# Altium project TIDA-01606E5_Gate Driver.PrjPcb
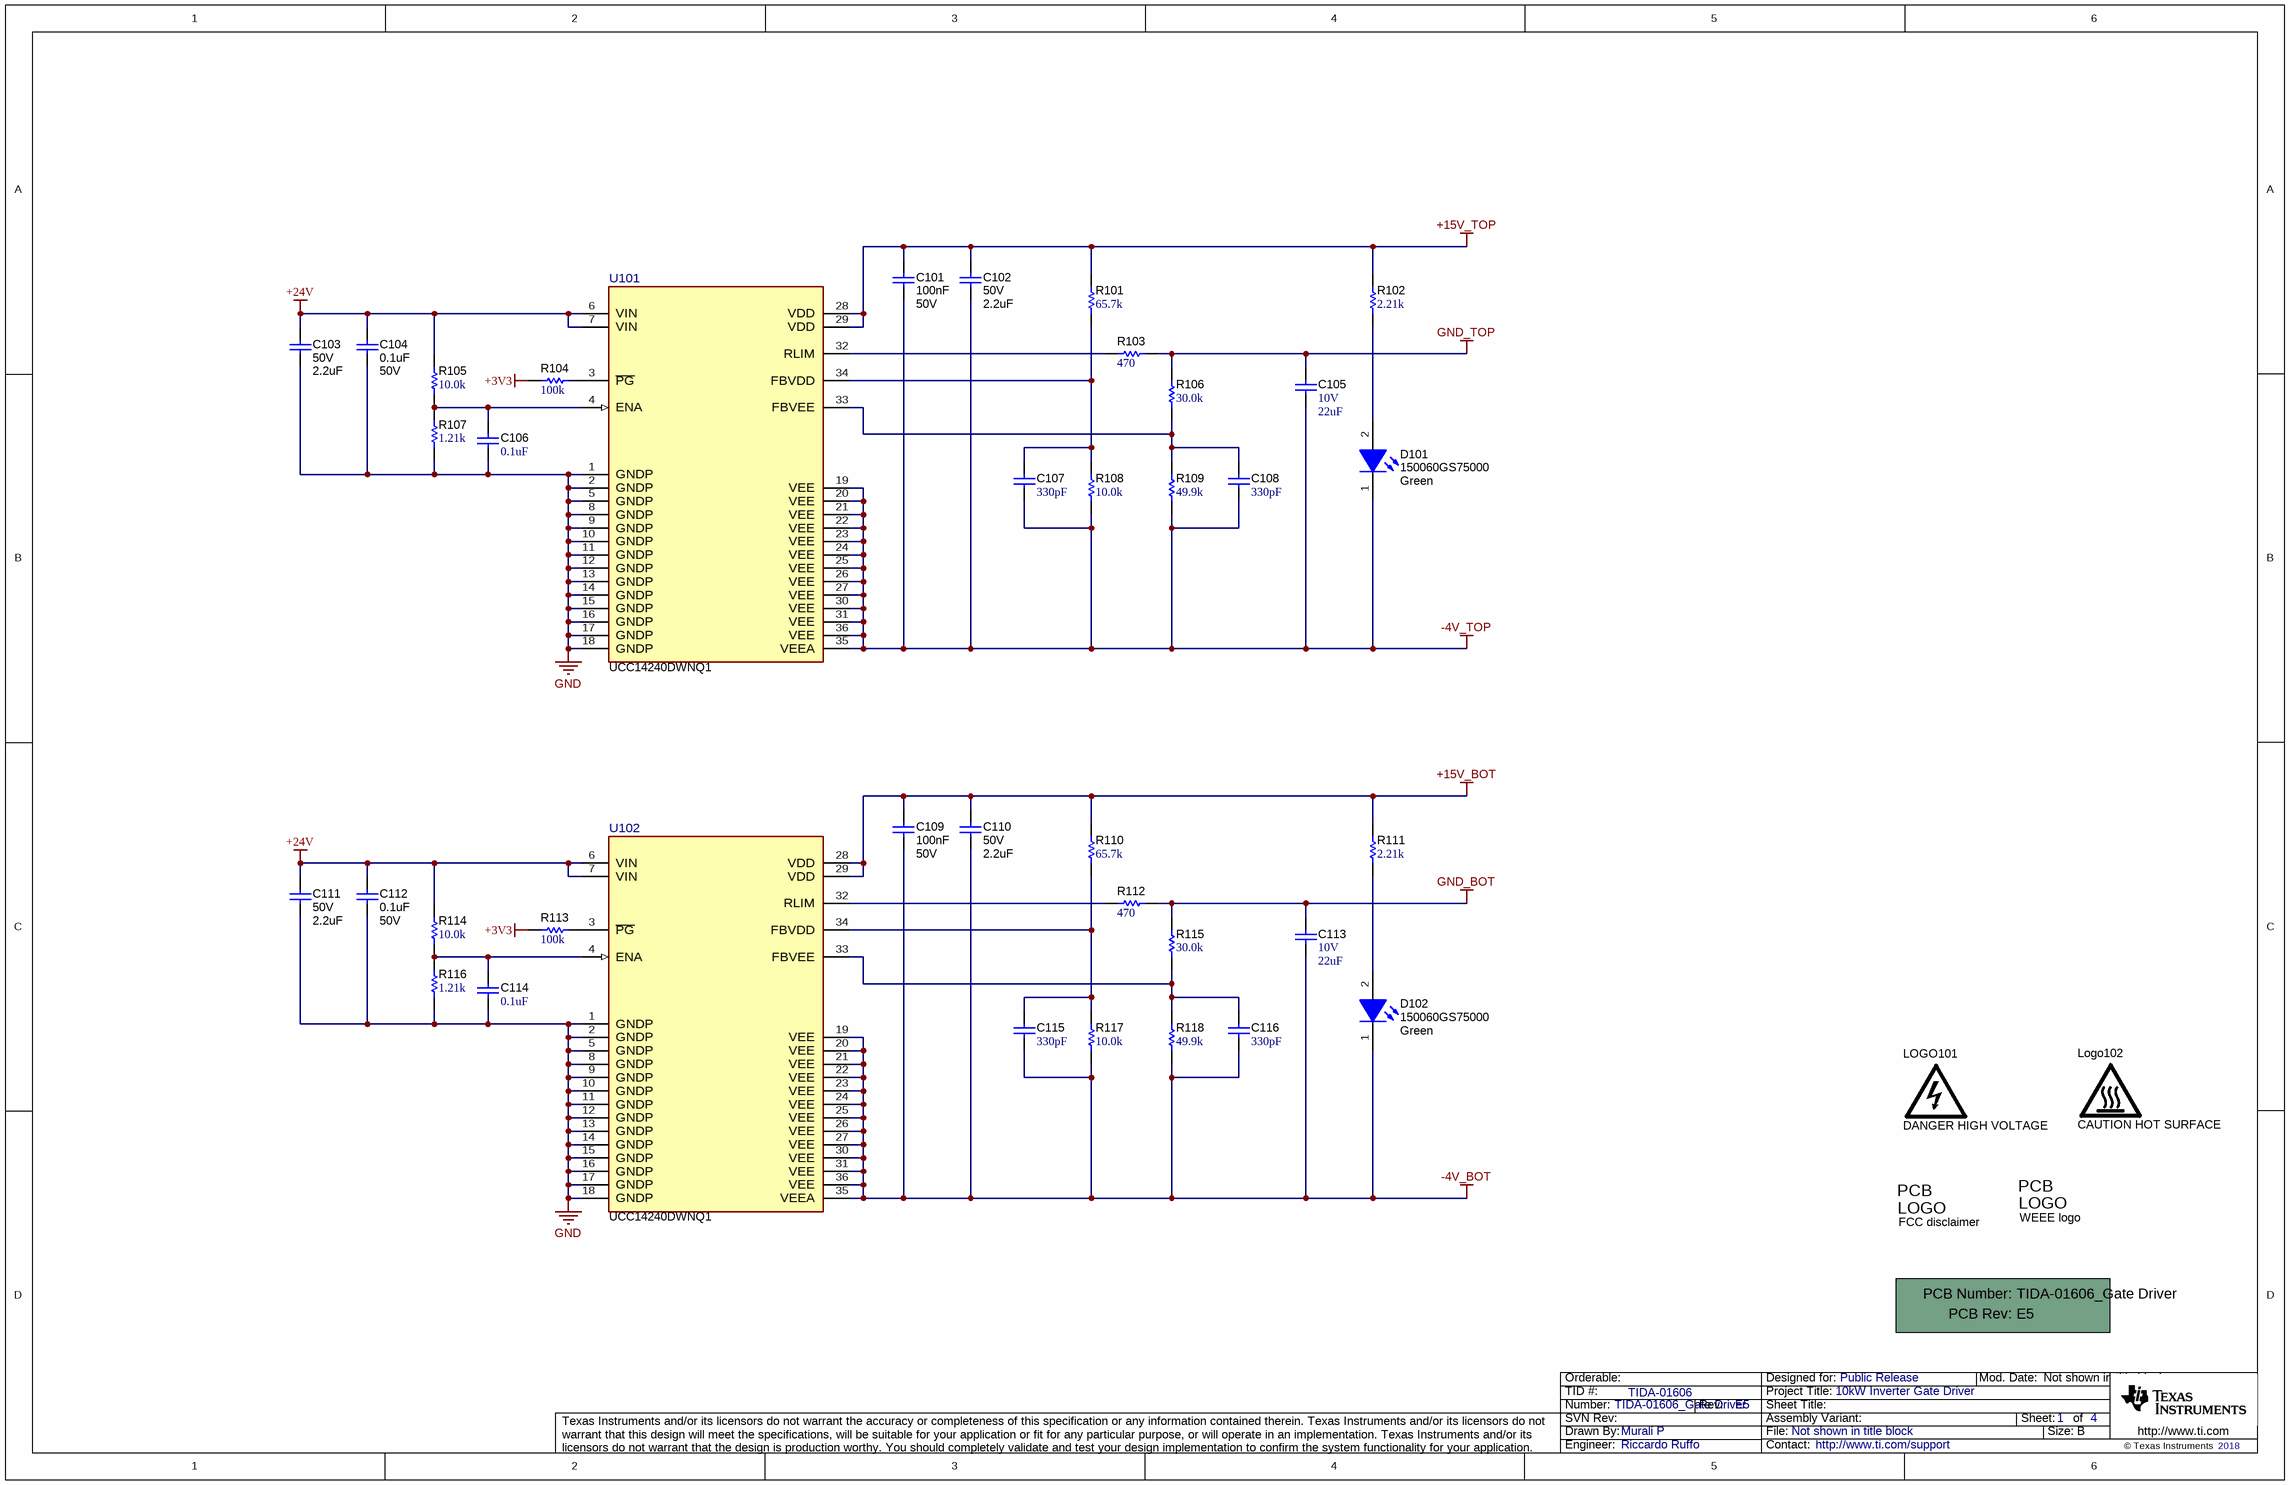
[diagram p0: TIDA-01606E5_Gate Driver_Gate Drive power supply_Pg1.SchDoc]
Drawn By: Riccardo Ruffo; TID: TIDA-01606; TechSupport: http://www.ti.com/support; SCH_Rev: E5; PRJ_Title: 10kW Inverter Gate Driver; PRJ_Number: TIDA-01606_Gate Driver; PRJ_Engineer: Riccardo Ruffo; PRJ_Customer: Public Release; PCB_Rev: E5; PCB_Layout: John Dorosa; CopyrightYear: 2018
4 sheets, 185 parts. Net scope: global (net labels, ports and power ports of the same name join across sheets).
Board file: TIDA-01606E5_Gate Driver_PCB.PcbDoc
Sheets:
  TIDA-01606E5_Gate Driver_Gate Drive power supply_Pg1.SchDoc
  TIDA-01606E5_Gate Driver_Gate Drive power supply_Pg2.SchDoc
  TIDA-01606E5_Gate Driver_Isolated Gate Driver_Pg3.SchDoc
  TIDA-01606E5_Gate Driver_Isolated Gate Driver_Pg4.SchDoc

## Sheet TIDA-01606E5_Gate Driver_Gate Drive power supply_Pg1.SchDoc
size 431 x 279 mm; Date: Not shown in title block; ApprovedBy: Not shown in title block; CheckedBy: Not shown in title block; Author: Not shown in title block; CompanyName: Not shown in title block; DrawnBy: Murali P; Engineer: Not shown in title block; Organization: Not shown in title block; Address1: Not shown in title block; Address2: Not shown in title block; Address3: Not shown in title block; Address4: Not shown in title block; DocumentNumber: 1; Revision: Use project parameter SCH_Rev; SheetNumber: 1; SheetTotal: 4; PageSetup: Record=PageOptions¦CenterHorizontal=True¦CenterVertical=True¦PrintScale=1.00¦XCorrection=1.00¦YCorrection=1.00¦PrintKind=0¦BorderSize=5000000¦LeftOffset=0¦BottomOffset=0¦Orientation=2¦PaperLength=1000¦PaperWidth=1000¦Scale=100¦PaperSource=15¦PrintQuality=600¦MediaType=1¦DitherType=10¦PaperKind=Letter¦PrintScaleMode=1

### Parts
!PCB101  Printed Circuit Board  (value not drawn)  (mechanical)
C101  Cap_F: 100nF  VDC_V: 50V  [0603]  (hidden comment: CGA3E2X7R1H104K080AA)
C102  VDC_V: 50V  ValueDisplayed: 2.2uF  [1210_280]  (hidden comment: C3225X7R1H225K250AB)
C103  VDC_V: 50V  ValueDisplayed: 2.2uF  [1210_280]  (hidden comment: C3225X7R1H225K250AB)
C104  value 0.1uF  VDC_V: 50V  [0603]  (hidden comment: CGA3E2X7R1H104K080AA)
C105  VDC_V: 10V  ValueDisplayed: 22uF  [1206_180L]  (hidden comment: GRM31CR71A226KE15L)
C106  ValueDisplayed: 0.1uF  [0402]  (hidden comment: GRM155R71A104KA01D)
C107  ValueDisplayed: 330pF  [0402]  (hidden comment: GRM155R71H331KA01D)
C108  ValueDisplayed: 330pF  [0402]  (hidden comment: GRM155R71H331KA01D)
C109  Cap_F: 100nF  VDC_V: 50V  [0603]  (hidden comment: CGA3E2X7R1H104K080AA)
C110  VDC_V: 50V  ValueDisplayed: 2.2uF  [1210_280]  (hidden comment: C3225X7R1H225K250AB)
C111  VDC_V: 50V  ValueDisplayed: 2.2uF  [1210_280]  (hidden comment: C3225X7R1H225K250AB)
C112  value 0.1uF  VDC_V: 50V  [0603]  (hidden comment: CGA3E2X7R1H104K080AA)
C113  VDC_V: 10V  ValueDisplayed: 22uF  [1206_180L]  (hidden comment: GRM31CR71A226KE15L)
C114  ValueDisplayed: 0.1uF  [0402]  (hidden comment: GRM155R71A104KA01D)
C115  ValueDisplayed: 330pF  [0402]  (hidden comment: GRM155R71H331KA01D)
C116  ValueDisplayed: 330pF  [0402]  (hidden comment: GRM155R71H331KA01D)
D101  150060GS75000  value Green  [WL-SMCW_GREEN]
D102  150060GS75000  value Green  [WL-SMCW_GREEN]
LOGO101  DANGER HIGH VOLTAGE  [IEC_HighVoltage_Small]  (no BOM)
Logo102  CAUTION HOT SURFACE  [IEC_HotSurface_Small]  (no BOM)
Logo103  WEEE logo  [WEEE_Minimum]  (no BOM)
Logo104  FCC disclaimer  [FCC_disclaimer]  (no BOM)
R101  ValueDisplayed: 65.7k  [0805_HV]  (hidden comment: RT0805BRD0765K7L)
R102  ValueDisplayed: 2.21k  [0402]  (hidden comment: CRCW04022K21FKED)
R103  ValueDisplayed: 470  [0402]  (hidden comment: ERJ-2RKF4700X)
R104  ValueDisplayed: 100k  [0402]  (hidden comment: CRCW0402100KFKED)
R105  ValueDisplayed: 10.0k  [0402]  (hidden comment: CRCW040210K0FKED)
R106  ValueDisplayed: 30.0k  [0402]  (hidden comment: CRCW040230K0FKED)
R107  ValueDisplayed: 1.21k  [0402]  (hidden comment: CRCW04021K21FKED)
R108  ValueDisplayed: 10.0k  [0402]  (hidden comment: CRCW040210K0FKED)
R109  ValueDisplayed: 49.9k  [0402]  (hidden comment: MCR01MZPF4992)
R110  ValueDisplayed: 65.7k  [0805_HV]  (hidden comment: RT0805BRD0765K7L)
R111  ValueDisplayed: 2.21k  [0402]  (hidden comment: CRCW04022K21FKED)
R112  ValueDisplayed: 470  [0402]  (hidden comment: ERJ-2RKF4700X)
R113  ValueDisplayed: 100k  [0402]  (hidden comment: CRCW0402100KFKED)
R114  ValueDisplayed: 10.0k  [0402]  (hidden comment: CRCW040210K0FKED)
R115  ValueDisplayed: 30.0k  [0402]  (hidden comment: CRCW040230K0FKED)
R116  ValueDisplayed: 1.21k  [0402]  (hidden comment: CRCW04021K21FKED)
R117  ValueDisplayed: 10.0k  [0402]  (hidden comment: CRCW040210K0FKED)
R118  ValueDisplayed: 49.9k  [0402]  (hidden comment: MCR01MZPF4992)
U101  UCC14240DWNQ1  [DWN0036-MFG]
U102  UCC14240DWNQ1  [DWN0036-MFG]

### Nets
+3V3: R104.1 R113.1
+15V_BOT: C109.1 C110.1 R110.2 R111.2 U102.28(VDD) U102.29(VDD)
+15V_TOP: C101.1 C102.1 R101.2 R102.2 U101.28(VDD) U101.29(VDD)
+24V: C103.1 C104.1 C111.1 C112.1 R105.2 R114.2 U101.6(VIN) U101.7(VIN) U102.6(VIN) U102.7(VIN)
-4V_BOT: C109.2 C110.2 C113.2 C115.1 C116.1 D102.1(K) R117.1 R118.1 U102.19(VEE) U102.20(VEE) U102.21(VEE) U102.22(VEE) U102.23(VEE) U102.24(VEE) U102.25(VEE) U102.26(VEE) U102.27(VEE) U102.30(VEE) U102.31(VEE) U102.35(VEEA) U102.36(VEE)
-4V_TOP: C101.2 C102.2 C105.2 C107.1 C108.1 D101.1(K) R108.1 R109.1 U101.19(VEE) U101.20(VEE) U101.21(VEE) U101.22(VEE) U101.23(VEE) U101.24(VEE) U101.25(VEE) U101.26(VEE) U101.27(VEE) U101.30(VEE) U101.31(VEE) U101.35(VEEA) U101.36(VEE)
GND: C103.2 C104.2 C106.2 C111.2 C112.2 C114.2 R107.1 R116.1 U101.1(GNDP) U101.2(GNDP) U101.5(GNDP) U101.8(GNDP) U101.9(GNDP) U101.10(GNDP) U101.11(GNDP) U101.12(GNDP) U101.13(GNDP) U101.14(GNDP) U101.15(GNDP) U101.16(GNDP) U101.17(GNDP) U101.18(GNDP) U102.1(GNDP) U102.2(GNDP) U102.5(GNDP) U102.8(GNDP) U102.9(GNDP) U102.10(GNDP) U102.11(GNDP) U102.12(GNDP) U102.13(GNDP) U102.14(GNDP) U102.15(GNDP) U102.16(GNDP) U102.17(GNDP) U102.18(GNDP)
GND_BOT: C113.1 R112.2 R115.2
GND_TOP: C105.1 R103.2 R106.2
NetC106_1: C106.1 R105.1 R107.2 U101.4(ENA)
NetC107_2: C107.2 R101.1 R108.2 U101.34(FBVDD)
NetC108_2: C108.2 R106.1 R109.2 U101.33(FBVEE)
NetC114_1: C114.1 R114.1 R116.2 U102.4(ENA)
NetC115_2: C115.2 R110.1 R117.2 U102.34(FBVDD)
NetC116_2: C116.2 R115.1 R118.2 U102.33(FBVEE)
NetD101_2: D101.2(A) R102.1
NetD102_2: D102.2(A) R111.1
NetR103_1: R103.1 U101.32(RLIM)
NetR104_2: R104.2 U101.3(~{PG})
NetR112_1: R112.1 U102.32(RLIM)
NetR113_2: R113.2 U102.3(~{PG})

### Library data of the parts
!PCB101 = CMP-0003618-2: Manufacturer: Any; PartNumber: TIDA-01606_Gate Driver
C101 C109 = CMP-0007078-4: CAP, CERM, 0.1 uF, 50 V, +/- 10%, X7R, AEC-Q200 Grade 1, 0603; Manufacturer: TDK; TaMin_C: -55°C; ESR_ohm: 29.6m; Polarized: N; SizeAreaWB_mm2: 4.68; Value1: 0.0296 ohm; U/M: EA; Value: 0.1uF; TaMax_C: 125°C; SizeZ_mm: 1; SizeX_mm: 1.6; SizeY_mm: 0.8; SizeArea_mm2: 1.28; AEC Qualified: Y; IRMS_A: 971.99mA; AEC Category: Q200
C102 C103 C110 C111 = CMP-0009122-1: CAP, CERM, 2.2 uF, 50 V, +/- 10%, X7R, 1210; Manufacturer: TDK; TaMin_C: -55°C; ESR_ohm: 5.36m; Polarized: N; SizeAreaWB_mm2: 14.7; Value1: 0.00536 ohm; U/M: EA; Value: 2.2uF; TaMax_C: 125°C; SizeZ_mm: 2.8; SizeX_mm: 3.2; SizeY_mm: 2.5; SizeArea_mm2: 8; Cap_F: 2.2µF; IRMS_A: 3.1778A; AEC Category: Q200
C104 C112 = CMP-0007078-4: CAP, CERM, 0.1 uF, 50 V, +/- 10%, X7R, AEC-Q200 Grade 1, 0603; Manufacturer: TDK; TaMin_C: -55°C; ESR_ohm: 29.6m; Polarized: N; SizeAreaWB_mm2: 4.68; Value1: 0.0296 ohm; U/M: EA; TaMax_C: 125°C; SizeZ_mm: 1; SizeX_mm: 1.6; SizeY_mm: 0.8; SizeArea_mm2: 1.28; AEC Qualified: Y; Cap_F: 100nF; IRMS_A: 971.99mA; AEC Category: Q200
C105 C113 = CMP-0008959-2: CAP, CERM, 22 uF, 10 V, +/- 10%, X7R, 1206; Manufacturer: MuRata; TaMin_C: -55°C; Polarized: N; SizeAreaWB_mm2: 10.92; Value1: Unknown; U/M: EA; Value: 22uF; TaMax_C: 125°C; SizeZ_mm: 1.8; SizeX_mm: 3.2; SizeY_mm: 1.6; Cap_Case: 1206; SizeArea_mm2: 5.12; Cap_F: 22µF; AEC Category: Q200
C106 C114 = CMP-0006629-2: CAP, CERM, 0.1 uF, 10 V, +/- 10%, X7R, 0402; Manufacturer: MuRata; TaMin_C: -55°C; Polarized: N; SizeAreaWB_mm2: 3; Value1: Unknown; U/M: EA; Value: 0.1uF; TaMax_C: 125°C; SizeZ_mm: 0.6; SizeX_mm: 1; SizeY_mm: 0.5; Value2: 10V; Cap_F: 100nF; AEC Category: Q200
C107 C108 C115 C116 = CMP-0006687-2: CAP, CERM, 330 pF, 50 V, +/- 10%, X7R, 0402; Manufacturer: MuRata; TaMin_C: -55°C; Polarized: N; SizeAreaWB_mm2: 3; Value1: Unknown; U/M: EA; Value: 330pF; TaMax_C: 125°C; SizeZ_mm: 0.6; SizeX_mm: 1; SizeY_mm: 0.5; Value2: 50V; AEC Category: Q200
D101 D102 = CMP-0002905-2: LED, Green, SMD; Manufacturer: Wurth Elektronik; Value1: W; Type: InGaN; Value2: 3.2V; Io_A: 20mA; Angle: 140; Tjmax_C: 85°C
LOGO101 = CMP-0074835-1: IEC 61010-1 High Voltage Warning; SymbolCreator: a0412235
Logo102 = CMP-0074837-2: IEC 61010-1 Hot Surface Warning; Manufacturer: Texas Instruments; CompType: IC; AEC Category: Q200; SymbolCreator: a0412235
Logo103 = CMP-0074769-1
Logo104 = CMP-0074847-1: FCC_disclaimer
R101 R110 = CMP-0020251-1: RES, 65.7 k, 0.1%, 0.125 W, 0805; Manufacturer: Yageo America; Power_W: 125mW; TempCo: 25 ppm/C; Value_Code: 65k7; U/M: EA; Value: 65.7k; EIA_Code: E192; SizeX_mm: 2; SizeY_mm: 1.25; SizeZ_mm: 1.45; Value2: 0.125W; SizeArea_mm2: 2.5; VDC_V: 150V; AEC Category: Q200
R102 R111 = CMP-0026232-2: RES, 2.21 k, 1%, 0.063 W, AEC-Q200 Grade 0, 0402; Manufacturer: Vishay-Dale; Power_W: 63mW; TempCo: 100 ppm/C; Value_Code: 2k21; Value: 2.21k; EIA_Code: E96; SizeX_mm: 1; SizeY_mm: 0.5; SizeZ_mm: 0.6; Value2: 0.063W; AEC Qualified: Y; VDC_V: 50V; AEC Category: Q200; AEC Grade: 0
R103 R112 = CMP-0026699-1: RES, 470, 1%, 0.1 W, AEC-Q200 Grade 0, 0402; Manufacturer: Panasonic; Power_W: 100mW; TempCo: 100 ppm/C; Value_Code: 470R; U/M: EA; Value: 470; SizeX_mm: 1; SizeY_mm: 0.5; SizeZ_mm: 0.6; Value2: 0.1W; AEC Qualified: Y; VDC_V: 50V; AEC Grade: 0; AEC Category: Q200
R104 R113 = CMP-0025950-3: RES, 100 k, 1%, 0.063 W, AEC-Q200 Grade 0, 0402; Manufacturer: Vishay-Dale; Power_W: 63mW; TempCo: 100 ppm/C; Value: 100k; EIA_Code: E96; SizeX_mm: 1; SizeY_mm: 0.5; SizeZ_mm: 0.6; Value2: 0.063W; AEC Qualified: Y; VDC_V: 50V; AEC Category: Q200; AEC Grade: 0
R105 R108 R114 R117 = CMP-0025958-3: RES, 10.0 k, 1%, 0.063 W, AEC-Q200 Grade 0, 0402; Manufacturer: Vishay-Dale; Power_W: 63mW; TempCo: 100 ppm/C; Value_Code: 10k0; Value: 10.0k; EIA_Code: E96; Res_ohm: 10k; SizeX_mm: 1; SizeY_mm: 0.5; SizeZ_mm: 0.6; Value2: 0.063W; AEC Qualified: Y; VDC_V: 50V; AEC Category: Q200; AEC Grade: 0
R106 R115 = CMP-0078244-2: RES, 30.0 k, 1%, 0.063 W, AEC-Q200 Grade 0, 0402; Manufacturer: Vishay-Dale; Power_W: 63mW; Green_Lifecycle: Active; TempCo: 100 ppm/C; Value_Code: 30k0; Green_REACh: Passed; Value: 30.0k; Res_ohm: 30k; SizeX_mm: 1; SizeY_mm: 0.5; SizeZ_mm: 0.6; Value2: 0.063W; AEC Qualified: Y; VDC_V: 50V; AEC Grade: 0; AEC Category: Q200
R107 R116 = CMP-0026079-3: RES, 1.21 k, 1%, 0.063 W, AEC-Q200 Grade 0, 0402; Manufacturer: Vishay-Dale; Power_W: 63mW; TempCo: 100 ppm/C; Value_Code: 1k21; Value: 1.21k; EIA_Code: E96; SizeX_mm: 1; SizeY_mm: 0.5; SizeZ_mm: 0.6; Value2: 0.063W; AEC Qualified: Y; VDC_V: 50V; AEC Category: Q200; AEC Grade: 0
R109 R118 = CMP-0026718-1: RES, 49.9 k, 1%, 0.063 W, 0402; Manufacturer: Rohm; Power_W: 63mW; TempCo: 100 ppm/C; Value_Code: 49k9; U/M: EA; Value: 49.9k; EIA_Code: E96; SizeX_mm: 1; SizeY_mm: 0.5; SizeZ_mm: 0.6; Value2: 0.063W; AEC Qualified: N; VDC_V: 50V; AEC Category: Q200
U101 U102 = CMP-0089786-7: 2W, 24V-Vin, 25V-Vout, High-Efficiency, >2. 5 kVRMS Isolated DC-DC Converter; Manufacturer: Texas Instruments; Max Supply Voltage: 27V; Standoff Height: 0.1mm; SizeZ_mm: 3.55mm; AEC Qualified: Yes; Output Voltage: 18-25/2.5-25V; TaMin_C: -40°C; CompType: IC; TJmax_C: +150°C; Min Supply Voltage: 21V; AEC Grade: Grade 1; Number Of Outputs: 2; Output Type: AdjustableProgrammable; TaMax_C: +125°C; AEC Category: Q200

## Sheet TIDA-01606E5_Gate Driver_Gate Drive power supply_Pg2.SchDoc
size 431 x 279 mm; Date: Not shown in title block; ApprovedBy: Not shown in title block; CheckedBy: Not shown in title block; Author: Not shown in title block; CompanyName: Not shown in title block; Engineer: Not shown in title block; Organization: Not shown in title block; Address1: Not shown in title block; Address2: Not shown in title block; Address3: Not shown in title block; Address4: Not shown in title block; DocumentNumber: 2; Revision: Use project parameter SCH_Rev; SheetNumber: 2; SheetTotal: 4; PageSetup: Record=PageOptions¦CenterHorizontal=True¦CenterVertical=True¦PrintScale=1.00¦XCorrection=1.00¦YCorrection=1.00¦PrintKind=0¦BorderSize=5000000¦LeftOffset=0¦BottomOffset=0¦Orientation=2¦PaperLength=1000¦PaperWidth=1000¦Scale=100¦PaperSource=15¦PrintQuality=600¦MediaType=1¦DitherType=10¦PaperKind=Letter¦PrintScaleMode=1
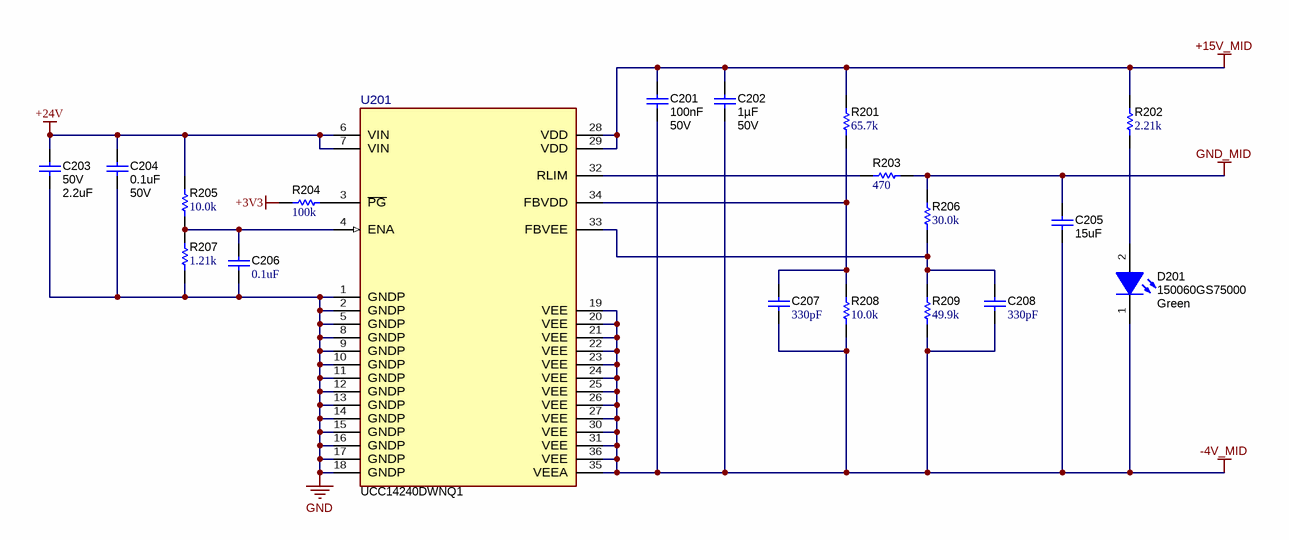
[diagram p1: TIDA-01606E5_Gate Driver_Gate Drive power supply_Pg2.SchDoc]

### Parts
C201  Cap_F: 100nF  VDC_V: 50V  [0603]  (hidden comment: CGA3E2X7R1H104K080AA)
C202  Cap_F: 1µF  VDC_V: 50V  [0603]  (hidden comment: UMK107AB7105KA-T)
C203  VDC_V: 50V  ValueDisplayed: 2.2uF  [1210_280]  (hidden comment: C3225X7R1H225K250AB)
C204  value 0.1uF  VDC_V: 50V  [0603]  (hidden comment: CGA3E2X7R1H104K080AA)
C205  ValueDisplayed: 15uF  [1206_180L]  (hidden comment: C3216X7S1A156M160AC)
C206  ValueDisplayed: 0.1uF  [0402]  (hidden comment: GRM155R71A104KA01D)
C207  ValueDisplayed: 330pF  [0402]  (hidden comment: GRM155R71H331KA01D)
C208  ValueDisplayed: 330pF  [0402]  (hidden comment: GRM155R71H331KA01D)
D201  150060GS75000  value Green  [WL-SMCW_GREEN]
R201  ValueDisplayed: 65.7k  [0805_HV]  (hidden comment: RT0805BRD0765K7L)
R202  ValueDisplayed: 2.21k  [0402]  (hidden comment: CRCW04022K21FKED)
R203  ValueDisplayed: 470  [0402]  (hidden comment: ERJ-2RKF4700X)
R204  ValueDisplayed: 100k  [0402]  (hidden comment: CRCW0402100KFKED)
R205  ValueDisplayed: 10.0k  [0402]  (hidden comment: CRCW040210K0FKED)
R206  ValueDisplayed: 30.0k  [0402]  (hidden comment: CRCW040230K0FKED)
R207  ValueDisplayed: 1.21k  [0402]  (hidden comment: CRCW04021K21FKED)
R208  ValueDisplayed: 10.0k  [0402]  (hidden comment: CRCW040210K0FKED)
R209  ValueDisplayed: 49.9k  [0402]  (hidden comment: MCR01MZPF4992)
U201  UCC14240DWNQ1  [DWN0036-MFG]

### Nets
+3V3: R204.1
+15V_MID: C201.1 C202.1 R201.2 R202.2 U201.28(VDD) U201.29(VDD)
+24V: C203.1 C204.1 R205.2 U201.6(VIN) U201.7(VIN)
-4V_MID: C201.2 C202.2 C205.2 C207.1 C208.1 D201.1(K) R208.1 R209.1 U201.19(VEE) U201.20(VEE) U201.21(VEE) U201.22(VEE) U201.23(VEE) U201.24(VEE) U201.25(VEE) U201.26(VEE) U201.27(VEE) U201.30(VEE) U201.31(VEE) U201.35(VEEA) U201.36(VEE)
GND: C203.2 C204.2 C206.2 R207.1 U201.1(GNDP) U201.2(GNDP) U201.5(GNDP) U201.8(GNDP) U201.9(GNDP) U201.10(GNDP) U201.11(GNDP) U201.12(GNDP) U201.13(GNDP) U201.14(GNDP) U201.15(GNDP) U201.16(GNDP) U201.17(GNDP) U201.18(GNDP)
GND_MID: C205.1 R203.2 R206.2
NetC206_1: C206.1 R205.1 R207.2 U201.4(ENA)
NetC207_2: C207.2 R201.1 R208.2 U201.34(FBVDD)
NetC208_2: C208.2 R206.1 R209.2 U201.33(FBVEE)
NetD201_2: D201.2(A) R202.1
NetR203_1: R203.1 U201.32(RLIM)
NetR204_2: R204.2 U201.3(~{PG})

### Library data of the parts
C201 = CMP-0007078-4: as C101 on sheet TIDA-01606E5_Gate Driver_Gate Drive power supply_Pg1
C202 = CMP-0007508-2: CAP, CERM, 1 uF, 50 V, +/- 10%, X7R, 0603; Manufacturer: Taiyo Yuden; TaMin_C: -55°C; Polarized: N; SizeAreaWB_mm2: 4.68; Value1: Unknown; U/M: EA; Value: 1uF; TaMax_C: 125°C; SizeZ_mm: 1; SizeX_mm: 1.6; SizeY_mm: 0.8; SizeArea_mm2: 1.28; AEC Category: Q200
C203 = CMP-0009122-1: as C102 on sheet TIDA-01606E5_Gate Driver_Gate Drive power supply_Pg1
C204 = CMP-0007078-4: as C104 on sheet TIDA-01606E5_Gate Driver_Gate Drive power supply_Pg1
C205 = CMP-0008721-2: CAP, CERM, 15 uF, 10 V, +/- 20%, X7S, 1206; Manufacturer: TDK; TaMin_C: -55°C; ESR_ohm: 2.667m; Polarized: N; SizeAreaWB_mm2: 10.92; Value1: 0.002667 ohm; U/M: EA; Value: 15uF; TaMax_C: 125°C; SizeZ_mm: 1.8; SizeX_mm: 3.2; SizeY_mm: 1.6; Cap_Case: 1206_180; Value2: 10V; SizeArea_mm2: 5.12; Cap_F: 15µF; IRMS_A: 4.4429A; AEC Category: Q200
C206 = CMP-0006629-2: as C106 on sheet TIDA-01606E5_Gate Driver_Gate Drive power supply_Pg1
C207 C208 = CMP-0006687-2: as C107 on sheet TIDA-01606E5_Gate Driver_Gate Drive power supply_Pg1
D201 = CMP-0002905-2: as D101 on sheet TIDA-01606E5_Gate Driver_Gate Drive power supply_Pg1
R201 = CMP-0020251-1: as R101 on sheet TIDA-01606E5_Gate Driver_Gate Drive power supply_Pg1
R202 = CMP-0026232-2: as R102 on sheet TIDA-01606E5_Gate Driver_Gate Drive power supply_Pg1
R203 = CMP-0026699-1: as R103 on sheet TIDA-01606E5_Gate Driver_Gate Drive power supply_Pg1
R204 = CMP-0025950-3: as R104 on sheet TIDA-01606E5_Gate Driver_Gate Drive power supply_Pg1
R205 R208 = CMP-0025958-3: as R105 on sheet TIDA-01606E5_Gate Driver_Gate Drive power supply_Pg1
R206 = CMP-0078244-2: as R106 on sheet TIDA-01606E5_Gate Driver_Gate Drive power supply_Pg1
R207 = CMP-0026079-3: as R107 on sheet TIDA-01606E5_Gate Driver_Gate Drive power supply_Pg1
R209 = CMP-0026718-1: as R109 on sheet TIDA-01606E5_Gate Driver_Gate Drive power supply_Pg1
U201 = CMP-0089786-7: as U101 on sheet TIDA-01606E5_Gate Driver_Gate Drive power supply_Pg1

## Sheet TIDA-01606E5_Gate Driver_Isolated Gate Driver_Pg3.SchDoc
size 431 x 279 mm; Date: Not shown in title block; ApprovedBy: Not shown in title block; CheckedBy: Not shown in title block; Author: Not shown in title block; CompanyName: Not shown in title block; DrawnBy: Murali P; Engineer: Not shown in title block; Organization: Not shown in title block; Address1: Not shown in title block; Address2: Not shown in title block; Address3: Not shown in title block; Address4: Not shown in title block; DocumentNumber: 3; Revision: Use project parameter SCH_Rev; SheetNumber: 3; SheetTotal: 4; PageSetup: Record=PageOptions¦CenterHorizontal=True¦CenterVertical=True¦PrintScale=1.00¦XCorrection=1.00¦YCorrection=1.00¦PrintKind=0¦BorderSize=5000000¦LeftOffset=0¦BottomOffset=0¦Orientation=2¦PaperLength=1000¦PaperWidth=1000¦Scale=100¦PaperSource=15¦PrintQuality=600¦MediaType=1¦DitherType=10¦PaperKind=Letter¦PrintScaleMode=1
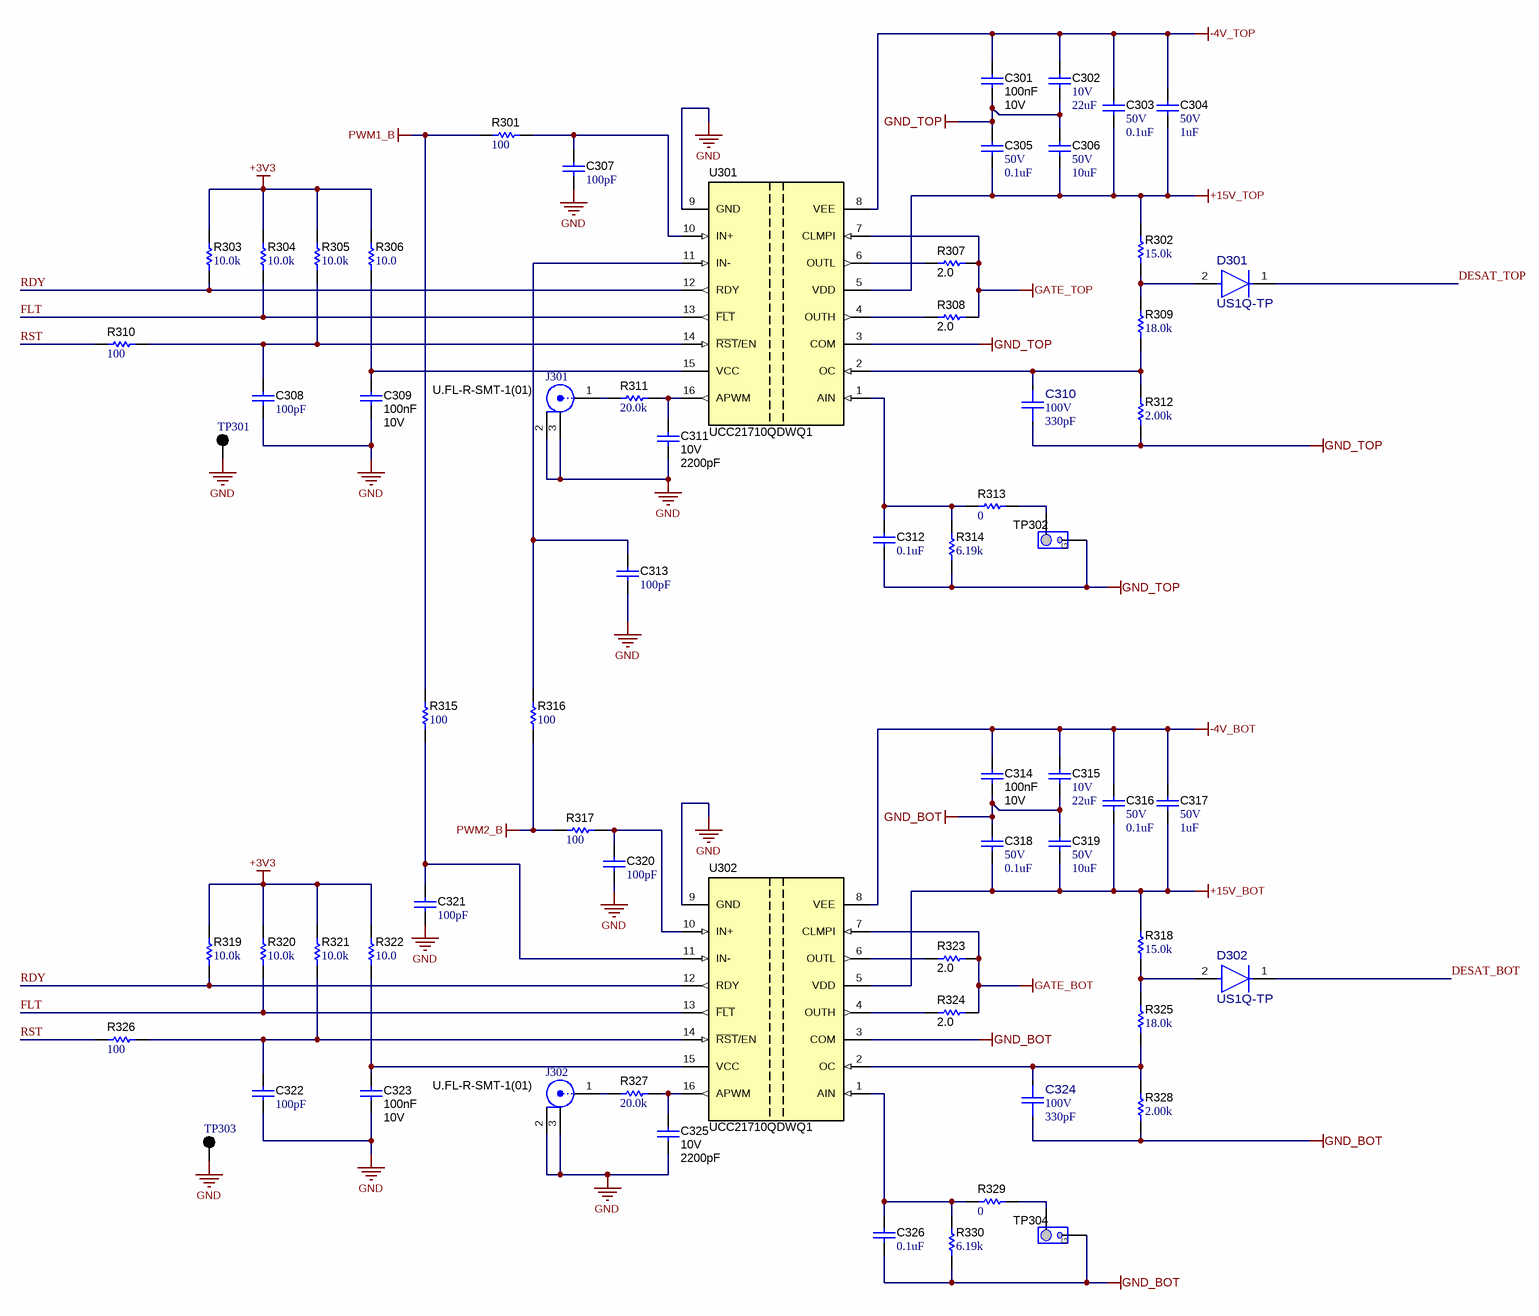
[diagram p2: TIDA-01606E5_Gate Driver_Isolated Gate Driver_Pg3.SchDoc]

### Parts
C301  Cap_F: 100nF  VDC_V: 10V  [0603]  (hidden comment: 0603ZC104KAT2A)
C302  VDC_V: 10V  ValueDisplayed: 22uF  [1206_180L]  (hidden comment: GRM31CR71A226KE15L)
C303  VDC_V: 50V  ValueDisplayed: 0.1uF  [1206L]  (hidden comment: GRM319R71H104KA01D)
C304  VDC_V: 50V  ValueDisplayed: 1uF  [1206L]  (hidden comment: GRM31MR71H105KA88L)
C305  VDC_V: 50V  ValueDisplayed: 0.1uF  [1206L]  (hidden comment: GRM319R71H104KA01D)
C306  VDC_V: 50V  ValueDisplayed: 10uF  [1206_180L]  (hidden comment: GRM31CR61H106KA12L)
C307  ValueDisplayed: 100pF  [0402]  (hidden comment: GRM1555C1H101JA01D)
C308  ValueDisplayed: 100pF  [0402]  (hidden comment: GRM1555C1H101JA01D)
C309  Cap_F: 100nF  VDC_V: 10V  [0603]  (hidden comment: 0603ZC104KAT2A)
C310  VDC_V: 100V  ValueDisplayed: 330pF  [FP-GCM155R72A331KA37D_0402-MFG]  (hidden comment: GCM155R72A331KA37D)
C311  VDC_V: 10V  ValueDisplayed: 2200pF  [0402]  (hidden comment: 885012205008)
C312  ValueDisplayed: 0.1uF  [0402]  (hidden comment: GRM155R71A104KA01D)
C313  ValueDisplayed: 100pF  [0805_HV]  (hidden comment: GRM2165C1H101JA01D)
C314  Cap_F: 100nF  VDC_V: 10V  [0603]  (hidden comment: 0603ZC104KAT2A)
C315  VDC_V: 10V  ValueDisplayed: 22uF  [1206_180L]  (hidden comment: GRM31CR71A226KE15L)
C316  VDC_V: 50V  ValueDisplayed: 0.1uF  [1206L]  (hidden comment: GRM319R71H104KA01D)
C317  VDC_V: 50V  ValueDisplayed: 1uF  [1206L]  (hidden comment: GRM31MR71H105KA88L)
C318  VDC_V: 50V  ValueDisplayed: 0.1uF  [1206L]  (hidden comment: GRM319R71H104KA01D)
C319  VDC_V: 50V  ValueDisplayed: 10uF  [1206_180L]  (hidden comment: GRM31CR61H106KA12L)
C320  ValueDisplayed: 100pF  [0402]  (hidden comment: GRM1555C1H101JA01D)
C321  ValueDisplayed: 100pF  [0805_HV]  (hidden comment: GRM2165C1H101JA01D)
C322  ValueDisplayed: 100pF  [0402]  (hidden comment: GRM1555C1H101JA01D)
C323  Cap_F: 100nF  VDC_V: 10V  [0603]  (hidden comment: 0603ZC104KAT2A)
C324  VDC_V: 100V  ValueDisplayed: 330pF  [FP-GCM155R72A331KA37D_0402-MFG]  (hidden comment: GCM155R72A331KA37D)
C325  VDC_V: 10V  ValueDisplayed: 2200pF  [0402]  (hidden comment: 885012205008)
C326  ValueDisplayed: 0.1uF  [0402]  (hidden comment: GRM155R71A104KA01D)
D301  US1Q-TP  [FP-US1Q-TP_SMA-MFG]
D302  US1Q-TP  [FP-US1Q-TP_SMA-MFG]
J301  U.FL-R-SMT-1(01)  [CONN_UFL-R-SMT-1]
J302  U.FL-R-SMT-1(01)  [CONN_UFL-R-SMT-1]
R301  ValueDisplayed: 100  [0402]  (hidden comment: CRCW0402100RFKED)
R302  ValueDisplayed: 15.0k  [1206]  (hidden comment: RC1206FR-0715KL)
R303  ValueDisplayed: 10.0k  [0402]  (hidden comment: CRCW040210K0FKED)
R304  ValueDisplayed: 10.0k  [0402]  (hidden comment: CRCW040210K0FKED)
R305  ValueDisplayed: 10.0k  [0402]  (hidden comment: CRCW040210K0FKED)
R306  ValueDisplayed: 10.0  [0402]  (hidden comment: CRCW040210R0FKED)
R307  ValueDisplayed: 2.0  [1206]  (hidden comment: CRCW12062R00JNEA)
R308  ValueDisplayed: 2.0  [1206]  (hidden comment: CRCW12062R00JNEA)
R309  ValueDisplayed: 18.0k  [0402]  (hidden comment: ERJ2RKF1802X)
R310  ValueDisplayed: 100  [0402]  (hidden comment: CRCW0402100RFKED)
R311  ValueDisplayed: 20.0k  [0402]  (hidden comment: CRCW040220K0FKED)
R312  ValueDisplayed: 2.00k  [0402]  (hidden comment: CRCW04022K00FKED)
R313  ValueDisplayed: 0  [0402]  (hidden comment: CRCW04020000Z0ED)
R314  ValueDisplayed: 6.19k  [0402]  (hidden comment: CRCW04026K19FKED)
R315  ValueDisplayed: 100  [0402]  (hidden comment: CRCW0402100RFKED)
R316  ValueDisplayed: 100  [0402]  (hidden comment: CRCW0402100RFKED)
R317  ValueDisplayed: 100  [0402]  (hidden comment: CRCW0402100RFKED)
R318  ValueDisplayed: 15.0k  [1206]  (hidden comment: RC1206FR-0715KL)
R319  ValueDisplayed: 10.0k  [0402]  (hidden comment: CRCW040210K0FKED)
R320  ValueDisplayed: 10.0k  [0402]  (hidden comment: CRCW040210K0FKED)
R321  ValueDisplayed: 10.0k  [0402]  (hidden comment: CRCW040210K0FKED)
R322  ValueDisplayed: 10.0  [0402]  (hidden comment: CRCW040210R0FKED)
R323  ValueDisplayed: 2.0  [1206]  (hidden comment: CRCW12062R00JNEA)
R324  ValueDisplayed: 2.0  [1206]  (hidden comment: CRCW12062R00JNEA)
R325  ValueDisplayed: 18.0k  [0402]  (hidden comment: ERJ2RKF1802X)
R326  ValueDisplayed: 100  [0402]  (hidden comment: CRCW0402100RFKED)
R327  ValueDisplayed: 20.0k  [0402]  (hidden comment: CRCW040220K0FKED)
R328  ValueDisplayed: 2.00k  [0402]  (hidden comment: CRCW04022K00FKED)
R329  ValueDisplayed: 0  [0402]  (hidden comment: CRCW04020000Z0ED)
R330  ValueDisplayed: 6.19k  [0402]  (hidden comment: CRCW04026K19FKED)
TP301  5001  [Keystone5001]  (value not drawn)
TP302  GNDP  [TESTPOINT_PIGTAIL]  (value not drawn)  (no BOM)
TP303  5001  [Keystone5001]  (value not drawn)
TP304  GNDP  [TESTPOINT_PIGTAIL]  (value not drawn)  (no BOM)
U301  UCC21710QDWQ1  [DW0016B_HV]
U302  UCC21710QDWQ1  [DW0016B_HV]

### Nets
+3V3: R303.2 R304.2 R305.2 R306.2 R319.2 R320.2 R321.2 R322.2
+15V_BOT: C316.2 C317.2 C318.2 C319.2 R318.2 U302.5(VDD)
+15V_TOP: C303.2 C304.2 C305.2 C306.2 R302.2 U301.5(VDD)
-4V_BOT: C314.2 C315.1 C316.1 C317.1 U302.8(VEE)
-4V_TOP: C301.2 C302.1 C303.1 C304.1 U301.8(VEE)
GATE_BOT: R323.2 R324.2 U302.7(CLMPI)
GATE_TOP: R307.2 R308.2 U301.7(CLMPI)
GND: C307.2 C308.2 C309.1 C311.1 C313.2 C320.2 C321.2 C322.2 C323.1 C325.1 J301.2 J301.3 J302.2 J302.3 TP301.1 TP303.1 U301.9(GND) U302.9(GND)
GND_BOT: C314.1 C315.2 C318.1 C319.1 C324.1 C326.2 R328.1 R330.1 TP304.2 U302.3(COM)
GND_TOP: C301.1 C302.2 C305.1 C306.1 C310.1 C312.2 R312.1 R314.1 TP302.2 U301.3(COM)
PWM1_B: R301.1 R315.2
PWM2_B: R316.1 R317.2
DESAT_BOT: D302.1(CATHODE)
DESAT_TOP: D301.1(CATHODE)
FLT: R304.1 R320.1 U301.13(~{FLT}) U302.13(~{FLT})
RDY: R303.1 R319.1 U301.12(RDY) U302.12(RDY)
RST: R310.1 R326.1
NetC307_1: C307.1 R301.2 U301.10(IN+)
NetC308_1: C308.1 R305.1 R310.2 U301.14(~{RST}/EN)
NetC309_2: C309.2 R306.1 U301.15(VCC)
NetC310_2: C310.2 R309.1 R312.2 U301.2(OC)
NetC311_2: C311.2 R311.2 U301.16(APWM)
NetC312_1: C312.1 R313.1 R314.2 U301.1(AIN)
NetC313_1: C313.1 R316.2 U301.11(IN-)
NetC320_1: C320.1 R317.1 U302.10(IN+)
NetC321_1: C321.1 R315.1 U302.11(IN-)
NetC322_1: C322.1 R321.1 R326.2 U302.14(~{RST}/EN)
NetC323_2: C323.2 R322.1 U302.15(VCC)
NetC324_2: C324.2 R325.1 R328.2 U302.2(OC)
NetC325_2: C325.2 R327.2 U302.16(APWM)
NetC326_1: C326.1 R329.1 R330.2 U302.1(AIN)
NetD301_2: D301.2(ANODE) R302.1 R309.2
NetD302_2: D302.2(ANODE) R318.1 R325.2
NetJ301_1: J301.1 R311.1
NetJ302_1: J302.1 R327.1
NetR307_1: R307.1 U301.6(OUTL)
NetR308_1: R308.1 U301.4(OUTH)
NetR313_2: R313.2 TP302.1
NetR323_1: R323.1 U302.6(OUTL)
NetR324_1: R324.1 U302.4(OUTH)
NetR329_2: R329.2 TP304.1

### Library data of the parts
C301 C309 C314 C323 = CMP-0006815-4: CAP, CERM, 0.1 uF, 10 V, +/- 10%, X7R, 0603; Manufacturer: AVX; TaMin_C: -55°C; Polarized: N; SizeAreaWB_mm2: 4.68; Value1: Unknown; U/M: EA; Value: 0.1uF; TaMax_C: 125°C; SizeZ_mm: 1; SizeX_mm: 1.6; SizeY_mm: 0.8; SizeArea_mm2: 1.28; AEC Category: Q200
C302 C315 = CMP-0008959-2: as C105 on sheet TIDA-01606E5_Gate Driver_Gate Drive power supply_Pg1
C303 C305 C316 C318 = CMP-0008876-2: CAP, CERM, 0.1 uF, 50 V, +/- 10%, X7R, 1206; Manufacturer: MuRata; TaMin_C: -55°C; ESR_ohm: 10m; Polarized: N; SizeAreaWB_mm2: 10.92; Value1: 0.01 ohm; U/M: EA; Value: 0.1uF; TaMax_C: 125°C; SizeZ_mm: 1.35; SizeX_mm: 3.2; SizeY_mm: 1.6; Cap_Case: 1206; SizeArea_mm2: 5.12; Cap_F: 100nF; IRMS_A: 900mA; AEC Category: Q200
C304 C317 = CMP-0008992-2: CAP, CERM, 1 uF, 50 V, +/- 10%, X7R, 1206; Manufacturer: MuRata; TaMin_C: -55°C; Polarized: N; SizeAreaWB_mm2: 10.92; Value1: Unknown; U/M: EA; Value: 1uF; TaMax_C: 125°C; SizeZ_mm: 1.35; SizeX_mm: 3.2; SizeY_mm: 1.6; Cap_Case: 1206; SizeArea_mm2: 5.12; Cap_F: 1µF; AEC Category: Q200
C306 C319 = CMP-0008954-3: CAP, CERM, 10 uF, 50 V, +/- 10%, X5R, 1206; Manufacturer: MuRata; Polarized: N; SizeY_mm: 1.6; SizeX_mm: 3.2; U/M: EA; Value1: Unknown; MFG_Status: TI_Obsolete; Value: 10uF; TaMax_C: 85°C; SizeAreaWB_mm2: 10.92; AEC Category: Q200; SizeArea_mm2: 5.12; TaMin_C: -55°C; Cap_Case: 1206; SizeZ_mm: 1.8; Cap_F: 10µF
C307 C308 C320 C322 = CMP-0006410-2: CAP, CERM, 100 pF, 50 V, +/- 5%, C0G/NP0, 0402; Manufacturer: MuRata; TaMin_C: -55°C; Polarized: N; SizeAreaWB_mm2: 3; Value1: Unknown; U/M: EA; Value: 100pF; TaMax_C: 125°C; SizeZ_mm: 0.6; SizeX_mm: 1; SizeY_mm: 0.5; Value2: 50V; AEC Category: Q200
C310 C324 = CMP-0088316-1: 330pF ±10% 100V Ceramic Capacitor X7R 0402 (1005 Metric); Manufacturer: Murata; TempCo: 15%; AEC Grade: Grade 1; AEC Qualified: Yes; SizeZ_mm: 0.55mm
C311 C325 = CMP-0006224-1: CAP, CERM, 2200 pF, 10 V, +/- 10%, X7R, 0402; Manufacturer: Wurth Elektronik; TaMin_C: -55°C; Polarized: N; SizeAreaWB_mm2: 3; Value1: Unknown; U/M: EA; Value: 2200pF; TaMax_C: 125°C; SizeZ_mm: 0.6; SizeX_mm: 1; SizeY_mm: 0.5; Cap_F: 2.2nF; AEC Category: Q200
C312 C326 = CMP-0006629-2: as C106 on sheet TIDA-01606E5_Gate Driver_Gate Drive power supply_Pg1
C313 C321 = CMP-0008059-2: CAP, CERM, 100 pF, 50 V, +/- 5%, C0G/NP0, 0805; Manufacturer: MuRata; TaMin_C: -55°C; Polarized: N; SizeAreaWB_mm2: 6.75; Value1: Unknown; U/M: EA; Value: 100pF; TaMax_C: 125°C; SizeZ_mm: 1.45; SizeX_mm: 2; SizeY_mm: 1.25; Cap_Case: 0805; Value2: 50V; SizeArea_mm2: 2.5; AEC Category: Q200
D301 D302 = CMP-0095286-1: Diode Standard 1200 V 1A Surface Mount DO-214AC (SMA); Manufacturer: MCC; Cap_F: 45pF; Max Surge Forward Current: 30A; SizeZ_mm: 2.44mm; TJmax_C: 150°C; Vr_V: 1.2kV; Peak Reverse Current: 5uA; AEC Qualified: No
J301 J302 = CMP-0075320-1: Receptacle, Ultra Miniature Coaxial, Male Pin, 50 ohm, SMT; Manufacturer: Hirose Electric Co. Ltd.; CNHeader: False; Gender: Female; ContactFinish: Gold
R301 R310 R315-R317 R326 = CMP-0025951-3: RES, 100, 1%, 0.063 W, AEC-Q200 Grade 0, 0402; Manufacturer: Vishay-Dale; Power_W: 63mW; TempCo: 100 ppm/C; Value_Code: 100R; Value: 100; EIA_Code: E96; SizeX_mm: 1; SizeY_mm: 0.5; SizeZ_mm: 0.6; Value2: 0.063W; AEC Qualified: Y; VDC_V: 50V; AEC Category: Q200; AEC Grade: 0
R302 R318 = CMP-0017916-2: RES, 15.0 k, 1%, 0.25 W, 1206; Manufacturer: Yageo America; Power_W: 250mW; TempCo: 100 ppm/C; Value_Code: 15k0; U/M: EA; Value: 15.0k; EIA_Code: E96; Res_ohm: 15k; SizeX_mm: 3.2; SizeY_mm: 1.6; SizeZ_mm: 1.35; Value2: 0.25W; SizeArea_mm2: 5.12; VDC_V: 200V; AEC Category: Q200
R303-R305 R319-R321 = CMP-0025958-3: as R105 on sheet TIDA-01606E5_Gate Driver_Gate Drive power supply_Pg1
R306 R322 = CMP-0025963-3: RES, 10.0, 1%, 0.063 W, AEC-Q200 Grade 0, 0402; Manufacturer: Vishay-Dale; Power_W: 63mW; TempCo: 100 ppm/C; Value_Code: 10R0; Value: 10.0; EIA_Code: E96; Res_ohm: 10; SizeX_mm: 1; SizeY_mm: 0.5; SizeZ_mm: 0.6; Value2: 0.063W; AEC Qualified: Y; VDC_V: 50V; AEC Category: Q200; AEC Grade: 0
R307 R308 R323 R324 = CMP-0018648-3: RES, 2.0, 5%, 0.25 W, AEC-Q200 Grade 0, 1206; Manufacturer: Vishay-Dale; Power_W: 250mW; TempCo: 200 ppm/C; Value_Code: 2R00; Value: 2.0; EIA_Code: E24; Res_ohm: 2; SizeX_mm: 3.2; SizeY_mm: 1.6; SizeZ_mm: 1.35; Value2: 0.25W; SizeArea_mm2: 5.12; AEC Qualified: Y; VDC_V: 200V; AEC Category: Q200; AEC Grade: 0
R309 R325 = CMP-0081723-1: RES, 18.0 k, 1%, 0.1 W, AEC-Q200 Grade 0, 0402; Manufacturer: Panasonic; Power_W: 100mW; TempCo: 100 ppm/C; SizeAreaWB_mm2: 3; Value_Code: 18k0; Value: 18.0k; Res_ohm: 18k; SizeX_mm: 1; SizeY_mm: 0.5; SizeZ_mm: 0.6; Value2: 0.1W; AEC Qualified: Y; AEC Grade: 0; AEC Category: Q200
R311 R327 = CMP-0026162-2: RES, 20.0 k, 1%, 0.063 W, AEC-Q200 Grade 0, 0402; Manufacturer: Vishay-Dale; Power_W: 63mW; TempCo: 100 ppm/C; Value_Code: 20k0; Value: 20.0k; EIA_Code: E96; Res_ohm: 20k; SizeX_mm: 1; SizeY_mm: 0.5; SizeZ_mm: 0.6; Value2: 0.063W; AEC Qualified: Y; VDC_V: 50V; AEC Category: Q200; AEC Grade: 0
R312 R328 = CMP-0026227-2: RES, 2.00 k, 1%, 0.063 W, AEC-Q200 Grade 0, 0402; Manufacturer: Vishay-Dale; Power_W: 63mW; TempCo: 100 ppm/C; Value_Code: 2k00; Value: 2.00k; EIA_Code: E96; Res_ohm: 2k; SizeX_mm: 1; SizeY_mm: 0.5; SizeZ_mm: 0.6; Value2: 0.063W; AEC Qualified: Y; VDC_V: 50V; AEC Category: Q200; AEC Grade: 0
R313 R329 = CMP-0026822-3: RES, 0, 5%, 0.063 W, AEC-Q200 Grade 0, 0402; Manufacturer: Vishay-Dale; Power_W: 63mW; TempCo: 200 ppm/C; Value_Code: 0000; Value: 0; EIA_Code: E24; SizeX_mm: 1; SizeY_mm: 0.5; SizeZ_mm: 0.6; Value2: 0.063W; AEC Qualified: Y; VDC_V: 50V; AEC Category: Q200
R314 R330 = CMP-0026513-2: RES, 6.19 k, 1%, 0.063 W, AEC-Q200 Grade 0, 0402; Manufacturer: Vishay-Dale; Power_W: 63mW; TempCo: 100 ppm/C; Value_Code: 6k19; Value: 6.19k; EIA_Code: E96; SizeX_mm: 1; SizeY_mm: 0.5; SizeZ_mm: 0.6; Value2: 0.063W; AEC Qualified: Y; VDC_V: 50V; AEC Category: Q200; AEC Grade: 0
TP301 TP303 = CMP-0055138-2: Test Point, Miniature, Black, TH; Manufacturer: Keystone Electronics; ContactFinish: Silver; CNHeader: FALSE; Green_Lifecycle: Active; Green_REACh: Passed; CT: TRUE
TP302 TP304 = CMP-0003907-1: PIGTAIL; Manufacturer: Texas Instruments; CompType: Test Point
U301 U302 = CMP-0080534-2: Single Channel Isolated Gate Driver for SiC/IGBT with Advanced Protection and High-CMTI, DW0016B (SOIC-16); Manufacturer: Texas Instruments; Alternate PartNumber: UCC21710QDWRQ1; SizeY_mm: 10.3; CompType: IC; AEC Qualified: Y; SizeArea_mm2: 107.12; SizeAreaWB_mm2: 152.52; SizeZ_mm: 2.65; SizeX_mm: 10.4; AEC Category: Q200

## Sheet TIDA-01606E5_Gate Driver_Isolated Gate Driver_Pg4.SchDoc
size A3; Date: Not shown in title block; ApprovedBy: Not shown in title block; CheckedBy: Not shown in title block; Author: Not shown in title block; CompanyName: Not shown in title block; Engineer: Not shown in title block; Organization: Not shown in title block; Address1: Not shown in title block; Address2: Not shown in title block; Address3: Not shown in title block; Address4: Not shown in title block; DocumentNumber: 4; Revision: Use project parameter SCH_Rev; SheetNumber: 4; SheetTotal: 4; PageSetup: Record=PageOptions¦CenterHorizontal=True¦CenterVertical=True¦PrintScale=0.69¦XCorrection=1.00¦YCorrection=1.00¦PrintKind=0¦BorderSize=5000000¦LeftOffset=0¦BottomOffset=0¦Orientation=2¦PaperLength=1000¦PaperWidth=1000¦Scale=100¦PaperSource=15¦PrintQuality=600¦MediaType=1¦DitherType=10¦PaperKind=Letter¦PrintScaleMode=1
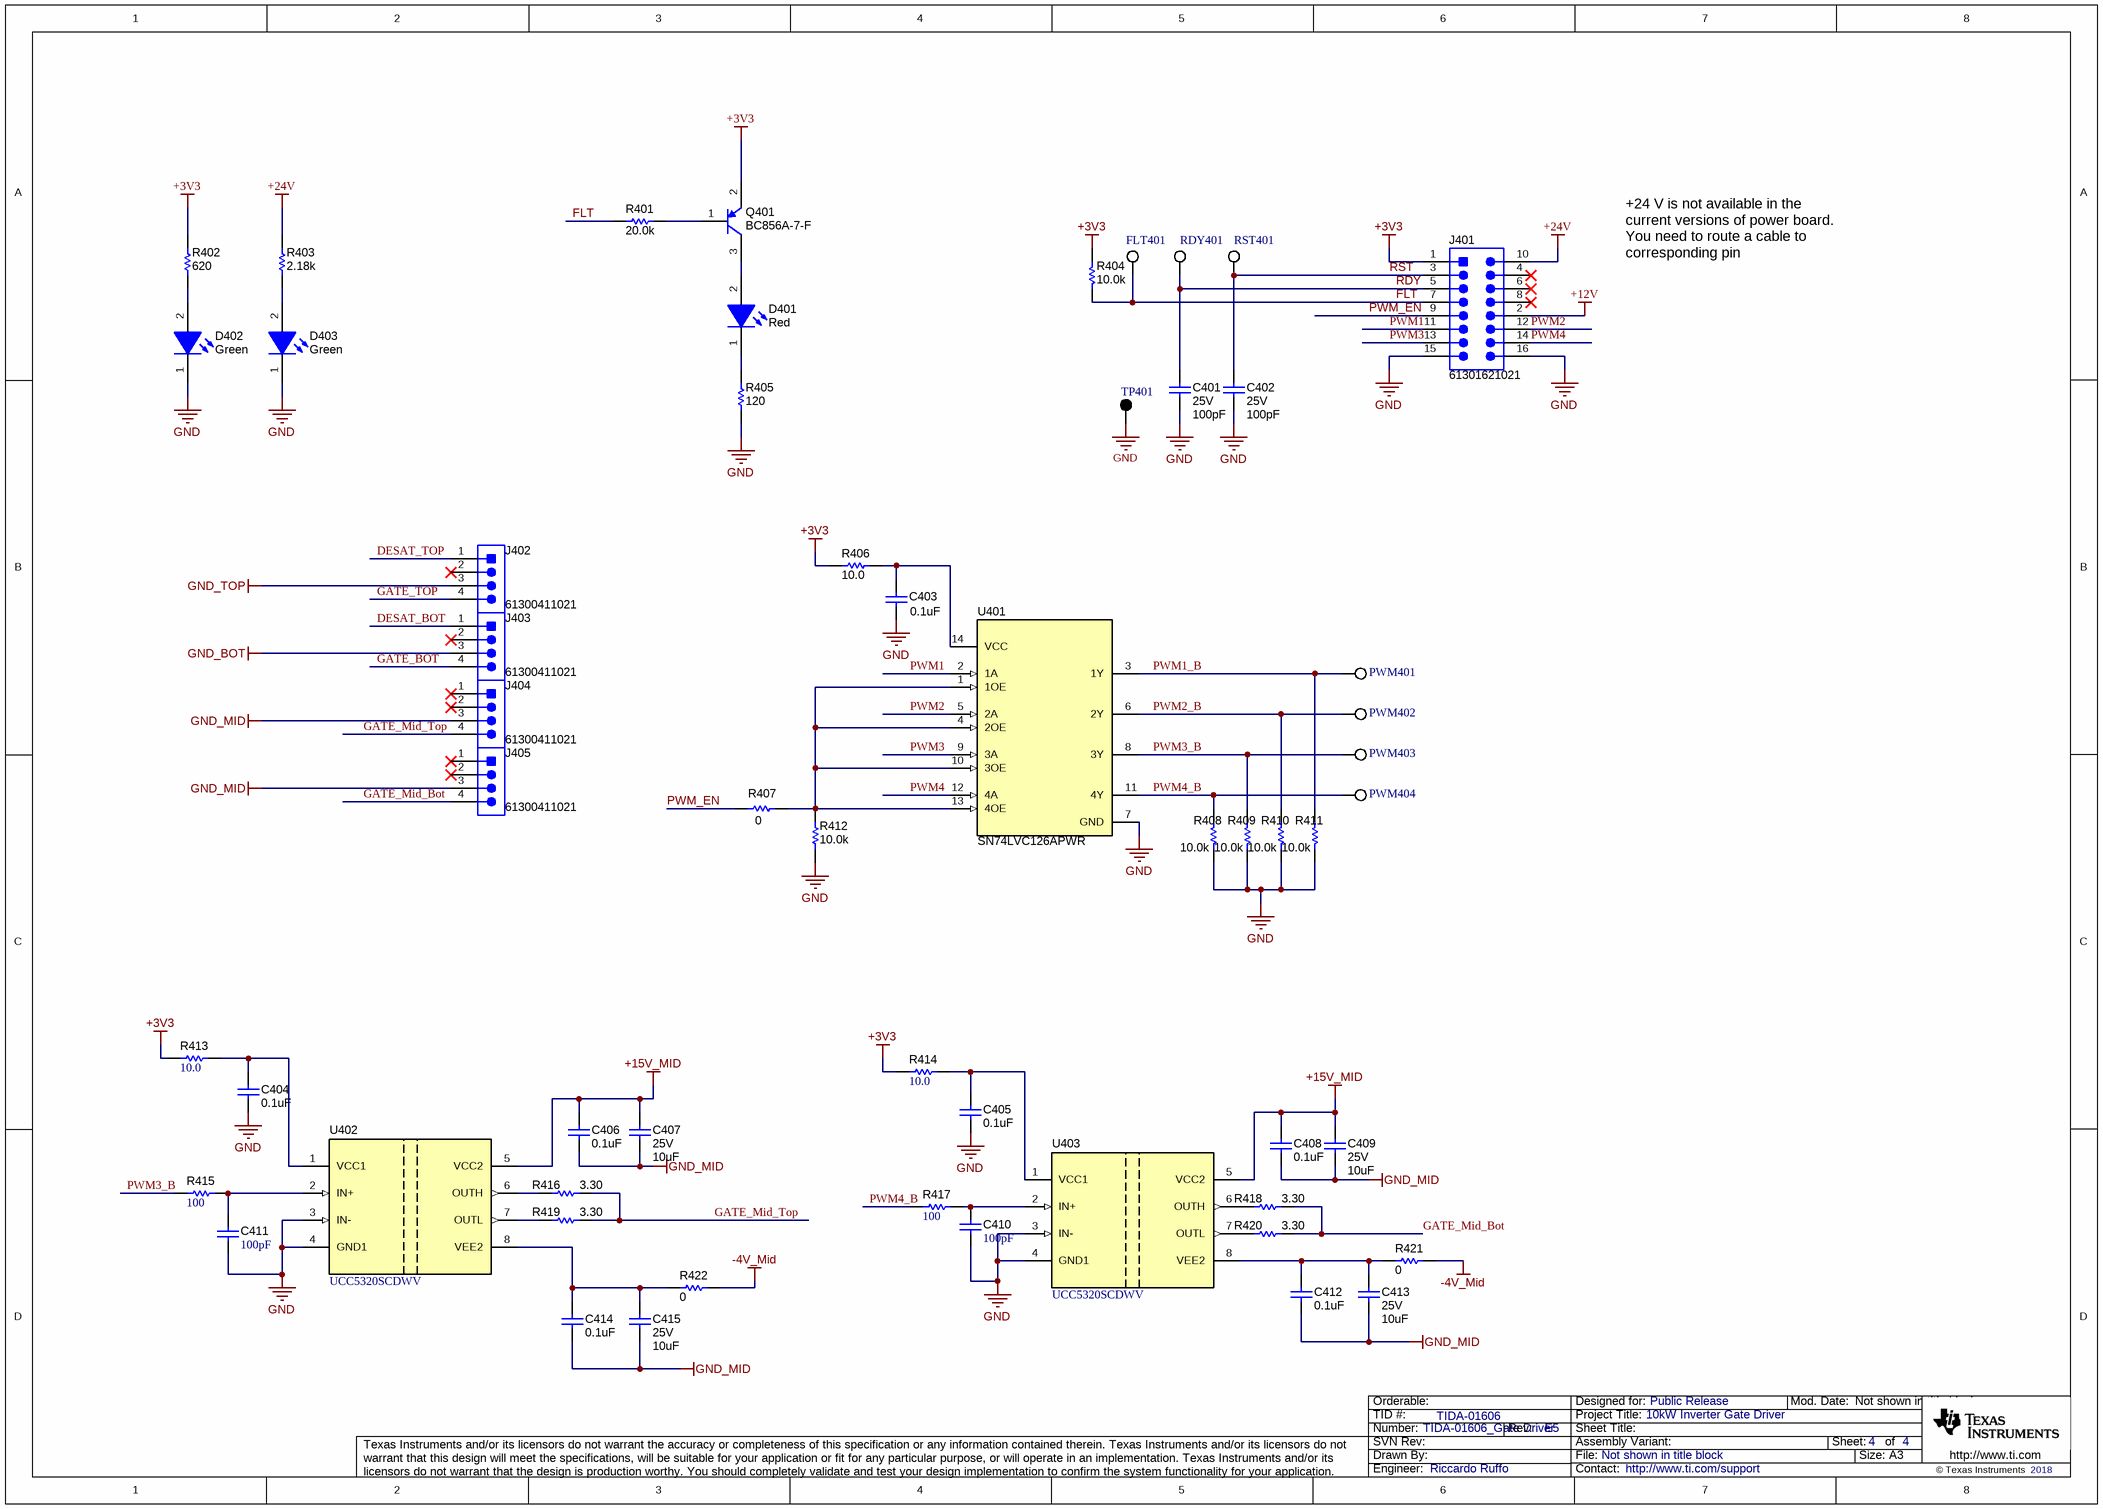
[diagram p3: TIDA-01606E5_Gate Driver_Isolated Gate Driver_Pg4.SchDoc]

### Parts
C401  VDC_V: 25V  ValueDisplayed: 100pF  [0402]  (hidden comment: C0402C101J3GACTU)
C402  VDC_V: 25V  ValueDisplayed: 100pF  [0402]  (hidden comment: C0402C101J3GACTU)
C403  ValueDisplayed: 0.1uF  [0603]  (hidden comment: 885012206095)
C404  ValueDisplayed: 0.1uF  [0402]  (hidden comment: GRM155R61H104ME14D)
C405  ValueDisplayed: 0.1uF  [0402]  (hidden comment: GRM155R61H104ME14D)
C406  ValueDisplayed: 0.1uF  [0402]  (hidden comment: GRM155R61H104ME14D)
C407  VDC_V: 25V  ValueDisplayed: 10uF  [0603]  (hidden comment: C1608X5R1E106M080AC)
C408  ValueDisplayed: 0.1uF  [0402]  (hidden comment: GRM155R61H104ME14D)
C409  VDC_V: 25V  ValueDisplayed: 10uF  [0603]  (hidden comment: C1608X5R1E106M080AC)
C410  ValueDisplayed: 100pF  [0402]  (hidden comment: GRM1555C1H101JA01D)
C411  ValueDisplayed: 100pF  [0402]  (hidden comment: GRM1555C1H101JA01D)
C412  ValueDisplayed: 0.1uF  [0402]  (hidden comment: GRM155R61H104ME14D)
C413  VDC_V: 25V  ValueDisplayed: 10uF  [0603]  (hidden comment: C1608X5R1E106M080AC)
C414  ValueDisplayed: 0.1uF  [0402]  (hidden comment: GRM155R61H104ME14D)
C415  VDC_V: 25V  ValueDisplayed: 10uF  [0603]  (hidden comment: C1608X5R1E106M080AC)
D401  value Red  [WL-SMCW_RED]  (hidden comment: 150060RS75000)
D402  value Green  [WL-SMCW_GREEN]  (hidden comment: 150060GS75000)
D403  value Green  [WL-SMCW_GREEN]  (hidden comment: 150060GS75000)
FLT401  5002  [Keystone5002]  (value not drawn)
J401  61301621021  [Wurth_61301621021]
J402  61300411021  [Wurth_61300411021]
J403  61300411021  [Wurth_61300411021]
J404  61300411021  [Wurth_61300411021]
J405  61300411021  [Wurth_61300411021]
PWM401  5002  [Keystone5002]  (value not drawn)
PWM402  5002  [Keystone5002]  (value not drawn)
PWM403  5002  [Keystone5002]  (value not drawn)
PWM404  5002  [Keystone5002]  (value not drawn)
Q401  BC856A-7-F  [SOT-23]
R401  ValueDisplayed: 20.0k  [0603]  (hidden comment: ERJ-3EKF2002V)
R402  ValueDisplayed: 620  [0603]  (hidden comment: RC0603FR-07620RL)
R403  ValueDisplayed: 2.18k  [0603]  (hidden comment: RT0603BRD072K18L)
R404  ValueDisplayed: 10.0k  [0603]  (hidden comment: CRCW060310K0FKEA)
R405  ValueDisplayed: 120  [0402]  (hidden comment: CRCW0402120RJNED)
R406  ValueDisplayed: 10.0  [0603]  (hidden comment: RC0603FR-0710RL)
R407  ValueDisplayed: 0  [0603]  (hidden comment: ERJ-3GEY0R00V)
R408  ValueDisplayed: 10.0k  [0603]  (hidden comment: CRCW060310K0FKEA)
R409  ValueDisplayed: 10.0k  [0603]  (hidden comment: CRCW060310K0FKEA)
R410  ValueDisplayed: 10.0k  [0603]  (hidden comment: CRCW060310K0FKEA)
R411  ValueDisplayed: 10.0k  [0603]  (hidden comment: CRCW060310K0FKEA)
R412  ValueDisplayed: 10.0k  [0603]  (hidden comment: CRCW060310K0FKEA)
R413  ValueDisplayed: 10.0  [0402]  (hidden comment: CRCW040210R0FKED)
R414  ValueDisplayed: 10.0  [0402]  (hidden comment: CRCW040210R0FKED)
R415  ValueDisplayed: 100  [0402]  (hidden comment: CRCW0402100RFKED)
R416  ValueDisplayed: 3.30  [1206]  (hidden comment: RC1206FR-073R3L)
R417  ValueDisplayed: 100  [0402]  (hidden comment: CRCW0402100RFKED)
R418  ValueDisplayed: 3.30  [1206]  (hidden comment: RC1206FR-073R3L)
R419  ValueDisplayed: 3.30  [1206]  (hidden comment: RC1206FR-073R3L)
R420  ValueDisplayed: 3.30  [1206]  (hidden comment: RC1206FR-073R3L)
R421  ValueDisplayed: 0  [0603]  (hidden comment: PMR03EZPJ000)
R422  ValueDisplayed: 0  [0603]  (hidden comment: PMR03EZPJ000)
RDY401  5002  [Keystone5002]  (value not drawn)
RST401  5002  [Keystone5002]  (value not drawn)
TP401  5001  [Keystone5001]  (value not drawn)
U401  SN74LVC126APWR  [PW0014A_N]
U402  UCC5320SCDWV  [DWV0008A]
U403  UCC5320SCDWV  [DWV0008A]

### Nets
+3V3: J401.1 Q401.2(E) R402.2 R404.2 R406.1 R413.1 R414.1
+12V: J401.2
+15V_MID: C406.1 C407.1 C408.1 C409.1 U402.5(VCC2) U403.5(VCC2)
+24V: J401.10 R403.2
-4V_MID: R421.2 R422.2
GATE_BOT: J403.4
GATE_TOP: J402.4
GND: C401.2 C402.2 C403.2 C404.2 C405.2 C410.2 C411.2 D402.1(K) D403.1(K) J401.15 J401.16 R405.1 R408.1 R409.1 R410.1 R411.1 R412.1 TP401.1 U401.7(GND) U402.3(IN-) U402.4(GND1) U403.3(IN-) U403.4(GND1)
GND_BOT: J403.3
GND_MID: C406.2 C407.2 C408.2 C409.2 C412.2 C413.2 C414.2 C415.2 J404.3 J405.3
GND_TOP: J402.3
PWM1_B: PWM401.1 R411.2 U401.3(1Y)
PWM2_B: PWM402.1 R410.2 U401.6(2Y)
DESAT_BOT: J403.1
DESAT_TOP: J402.1
FLT: FLT401.1 J401.7 R401.1 R404.1
GATE_Mid_Bot: J405.4 R418.2 R420.2
GATE_Mid_Top: J404.4 R416.2 R419.2
PWM1: J401.11 U401.2(1A)
PWM2: J401.12 U401.5(2A)
PWM3: J401.13 U401.9(3A)
PWM3_B: PWM403.1 R409.2 R415.1 U401.8(3Y)
PWM4: J401.14 U401.12(4A)
PWM4_B: PWM404.1 R408.2 R417.1 U401.11(4Y)
PWM_EN: J401.9 R407.1
RDY: C401.1 J401.5 RDY401.1
RST: C402.1 J401.3 RST401.1
NetC403_1: C403.1 R406.2 U401.14(VCC)
NetC404_1: C404.1 R413.2 U402.1(VCC1)
NetC405_1: C405.1 R414.2 U403.1(VCC1)
NetC410_1: C410.1 R417.2 U403.2(IN+)
NetC411_1: C411.1 R415.2 U402.2(IN+)
NetC412_1: C412.1 C413.1 R421.1 U403.8(VEE2)
NetC414_1: C414.1 C415.1 R422.1 U402.8(VEE2)
NetD401_1: D401.1(K) R405.2
NetD401_2: D401.2(A) Q401.3(C)
NetD402_2: D402.2(A) R402.1
NetD403_2: D403.2(A) R403.1
NetQ401_1: Q401.1(B) R401.2
NetR407_2: R407.2 R412.2 U401.1(1OE) U401.4(2OE) U401.10(3OE) U401.13(4OE)
NetR416_1: R416.1 U402.6(OUTH)
NetR418_1: R418.1 U403.6(OUTH)
NetR419_1: R419.1 U402.7(OUTL)
NetR420_1: R420.1 U403.7(OUTL)

Not connected (* = marked no-connect by the designer): J401 4* 6* 8*; J402 2*; J403 2*; J404 1* 2*; J405 1* 2*

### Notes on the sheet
- +24 V is not available in the current versions of power board.
  You need to route a cable to corresponding pin

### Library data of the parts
C401 C402 = CMP-0006233-2: CAP, CERM, 100 pF, 25 V, +/- 5%, C0G/NP0, 0402; Manufacturer: Kemet; TaMin_C: -55°C; Polarized: N; SizeAreaWB_mm2: 3; Value1: Unknown; U/M: EA; Value: 100pF; TaMax_C: 125°C; SizeZ_mm: 0.6; SizeX_mm: 1; SizeY_mm: 0.5; AEC Category: Q200
C403 = CMP-0006837-4: CAP, CERM, 0.1 uF, 50 V, +/- 10%, X7R, 0603; Manufacturer: Wurth Elektronik; TaMin_C: -55°C; Polarized: N; SizeAreaWB_mm2: 4.68; Value1: Unknown; U/M: EA; Value: 0.1uF; TaMax_C: 125°C; SizeZ_mm: 1; SizeX_mm: 1.6; SizeY_mm: 0.8; Value2: 50V; SizeArea_mm2: 1.28; CompType: Capacitor; Cap_F: 100nF; AEC Category: Q200
C404-C406 C408 C412 C414 = CMP-0006614-2: CAP, CERM, 0.1 uF, 50 V, +/- 20%, X5R, 0402; Manufacturer: MuRata; TaMin_C: -55°C; Polarized: N; SizeAreaWB_mm2: 3; Value1: Unknown; U/M: EA; Value: 0.1uF; TaMax_C: 85°C; SizeZ_mm: 0.6; SizeX_mm: 1; SizeY_mm: 0.5; Value2: 50V; Cap_F: 100nF; AEC Category: Q200
C407 C409 C413 C415 = CMP-0007007-1: CAP, CERM, 10 uF, 25 V, +/- 20%, X5R, 0603; Manufacturer: TDK; TaMin_C: -55°C; ESR_ohm: 4.639m; Polarized: N; SizeAreaWB_mm2: 4.68; Value1: 0.004639 ohm; U/M: EA; Value: 10uF; TaMax_C: 85°C; SizeZ_mm: 1; SizeX_mm: 1.6; SizeY_mm: 0.8; SizeArea_mm2: 1.28; Cap_F: 10µF; IRMS_A: 2.4141A; AEC Category: Q200
C410 C411 = CMP-0006410-2: as C307 on sheet TIDA-01606E5_Gate Driver_Isolated Gate Driver_Pg3
D401 = CMP-0002947-2: LED, Red, SMD; Manufacturer: Wurth Elektronik; Type: AlInGaP; Vf_V: 2V; Io_A: 30mA; Vr_V: 5V; Tjmax_C: 85°C; Power_TotalModule: 72mW; Value1: 0.072W; Angle: 140; U/M: EA
D402 D403 = CMP-0002905-1: LED, Green, SMD; Manufacturer: Wurth Elektronik; Type: InGaN; Vf_V: 3.2V; Io_A: 20mA; Tjmax_C: 85°C; Value1: W; Angle: 140; U/M: EA
FLT401 PWM401-PWM404 RDY401 RST401 = CMP-0055139-1: Test Point, Miniature, White, TH; Manufacturer: Keystone; ContactFinish: Silver; Green_Lifecycle: Active; Green_REACh: Passed; CNHeader: FALSE; CT: TRUE
J401 = CMP-0081505-1: Header, 2.54mm, 8x2, Gold, R/A, TH; Manufacturer: Wurth Elektronik; Pitch_mm: 2.54; Gender: Male; Cert_UL: Y; Current_A: 3A; Voltage_V: 250V; Shrouded: N; Row_Count: 2
J402-J405 = CMP-0054797-1: Header, 2.54 mm, 4x1, Gold, R/A, TH; Manufacturer: Wurth Elektronik; CNHeader: TRUE; Shrouded: N; Gender: Male; Row_Count: 1; Pitch_mm: 2.54; CT: FALSE
Q401 = CMP-0000314-2: Transistor, PNP, 65 V, 0.01 A, SOT-23; Manufacturer: Diodes Inc.; CompType: BJT; PNP: 1; NPN: 0; Vceo_V: 65V; Vcesat1_V: 3dV; Value: 65 V; IcRated_A: 10mA; Value1: 0.01 A; TaMin_C: -65°C; TaMax_C: 150°C; SizeAreaWB_mm2: 14; SizeArea_mm2: 7.5; SizeX_mm: 2.5; SizeY_mm: 3; SizeZ_mm: 1.1; U/M: EA; AEC Category: Q101
R401 = CMP-0022691-3: RES, 20.0 k, 1%, 0.1 W, AEC-Q200 Grade 0, 0603; Manufacturer: Panasonic; Value: 20.0k; Res_ohm: 20k; Value_Code: 20k0; Power_W: 100mW; Value2: 0.1W; VDC_V: 75V; TempCo: 100 ppm/C; SizeArea_mm2: 1.28; SizeX_mm: 1.6; SizeY_mm: 0.8; SizeZ_mm: 1; EIA_Code: E96; AEC Category: Q200; AEC Qualified: Y; AEC Grade: 0; U/M: EA
R402 = CMP-0023219-5: RES, 620, 1%, 0.1 W, 0603; Manufacturer: Yageo; Value: 620; Value_Code: 620R; Power_W: 100mW; Value2: 0.1W; VDC_V: 75V; TempCo: 100 ppm/C; SizeArea_mm2: 1.28; SizeX_mm: 1.6; SizeY_mm: 0.8; SizeZ_mm: 1; AEC Category: Q200; AEC Qualified: N; SizeAreaWB_mm2: 4.68
R403 = CMP-0024061-1: RES, 2.18 k, 0.1%, 0.1 W, 0603; Manufacturer: Yageo America; Power_W: 100mW; TempCo: 25 ppm/C; Value_Code: 2k18; U/M: EA; Value: 2.18k; EIA_Code: E192; SizeX_mm: 1.6; SizeY_mm: 0.8; SizeZ_mm: 1; Value2: 0.1W; SizeArea_mm2: 1.28; VDC_V: 75V; AEC Category: Q200
R404 R408-R412 = CMP-0021998-4: RES, 10.0 k, 1%, 0.1 W, AEC-Q200 Grade 0, 0603; Manufacturer: Vishay-Dale; Value: 10.0k; Res_ohm: 10k; Value_Code: 10k0; Power_W: 100mW; Value2: 0.1W; VDC_V: 75V; TempCo: 100 ppm/C; SizeArea_mm2: 1.28; SizeX_mm: 1.6; SizeY_mm: 0.8; SizeZ_mm: 1; EIA_Code: E96; AEC Category: Q200; AEC Qualified: Y; AEC Grade: 0
R405 = CMP-0026833-3: RES, 120, 5%, 0.063 W, AEC-Q200 Grade 0, 0402; Manufacturer: Vishay-Dale; Power_W: 63mW; TempCo: 200 ppm/C; Value_Code: 120R; Value: 120; EIA_Code: E24; SizeX_mm: 1; SizeY_mm: 0.5; SizeZ_mm: 0.6; Value2: 0.063W; CompType: Resistor; AEC Qualified: Y; VDC_V: 50V; AEC Category: Q200; AEC Grade: 0
R406 = CMP-0022751-4: RES, 10.0, 1%, 0.1 W, 0603; Manufacturer: Yageo; Value: 10.0; Res_ohm: 10; Value_Code: 10R0; Power_W: 100mW; Value2: 0.1W; VDC_V: 75V; TempCo: 100 ppm/C; SizeArea_mm2: 1.28; SizeX_mm: 1.6; SizeY_mm: 0.8; SizeZ_mm: 1; EIA_Code: E96; AEC Category: Q200; AEC Qualified: N; SizeAreaWB_mm2: 4.68
R407 = CMP-0025874-4: RES, 0, 5%, 0.1 W, AEC-Q200 Grade 0, 0603; Manufacturer: Panasonic; Value: 0; Value_Code: 0000; Power_W: 100mW; Value2: 0.1W; VDC_V: 50V; TempCo: 600 ppm/C; SizeArea_mm2: 1.28; SizeX_mm: 1.6; SizeY_mm: 0.8; SizeZ_mm: 1; EIA_Code: E24; AEC Category: Q200; AEC Qualified: Y; SizeAreaWB_mm2: 4.68
R413 R414 = CMP-0025963-3: as R306 on sheet TIDA-01606E5_Gate Driver_Isolated Gate Driver_Pg3
R415 R417 = CMP-0025951-3: as R301 on sheet TIDA-01606E5_Gate Driver_Isolated Gate Driver_Pg3
R416 R418-R420 = CMP-0018270-2: RES, 3.30, 1%, 0.25 W, 1206; Manufacturer: Yageo America; Value: 3.30; Res_ohm: 3.3; Value_Code: 3R30; Power_W: 250mW; Value2: 0.25W; VDC_V: 200V; TempCo: 200 ppm/C; SizeArea_mm2: 5.12; SizeX_mm: 3.2; SizeY_mm: 1.6; SizeZ_mm: 1.35; U/M: EA; AEC Category: Q200
R421 R422 = CMP-0086358-1: RES, 0, 0%, 0.25 W, AEC-Q200 Grade 0, 0603; Manufacturer: Rohm; Power_W: 250mW; SizeZ_mm: 1; SizeArea_mm2: 1.28; Value2: 0.25W; SizeAreaWB_mm2: 4.68; Value_Code: 0000; Value: 0; AEC Qualified: Y; AEC Category: Q200; SizeX_mm: 1.6; SizeY_mm: 0.8
TP401 = CMP-0055138-2: as TP301 on sheet TIDA-01606E5_Gate Driver_Isolated Gate Driver_Pg3
U401 = CMP-0066280-1: Quadruple Bus Buffer Gate with 3-State Outputs, PW0014A (TSSOP-14); Manufacturer: Texas Instruments; SizeArea_mm2: 32.0; SizeAreaWB_mm2: 58.8; SizeX_mm: 6.4; SizeY_mm: 5.0; SizeZ_mm: 1.2; CompType: IC; U/M: EA
U402 U403 = CMP-0078838-1: 5-kVRMS Single-Channel Isolated Gate Drivers, DWV0008A (SOIC-8); Alternate PartNumber: UCC5320SCDWVR; Alternate Manufacturer: Texas Instruments; SizeAreaWB_mm2: 105.975; SizeZ_mm: 2.8; SizeX_mm: 11.5; SizeY_mm: 5.85; SizeArea_mm2: 67.275; CompType: IC; AEC Qualified: N; AEC Category: Q200

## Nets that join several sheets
+3V3: TIDA-01606E5_Gate Driver_Gate Drive power supply_Pg1 (R104.1 R113.1), TIDA-01606E5_Gate Driver_Gate Drive power supply_Pg2 (R204.1), TIDA-01606E5_Gate Driver_Isolated Gate Driver_Pg3 (8 pins), TIDA-01606E5_Gate Driver_Isolated Gate Driver_Pg4 (7 pins)
+15V_BOT: TIDA-01606E5_Gate Driver_Gate Drive power supply_Pg1 (6 pins), TIDA-01606E5_Gate Driver_Isolated Gate Driver_Pg3 (6 pins)
+15V_MID: TIDA-01606E5_Gate Driver_Gate Drive power supply_Pg2 (6 pins), TIDA-01606E5_Gate Driver_Isolated Gate Driver_Pg4 (6 pins)
+15V_TOP: TIDA-01606E5_Gate Driver_Gate Drive power supply_Pg1 (6 pins), TIDA-01606E5_Gate Driver_Isolated Gate Driver_Pg3 (6 pins)
+24V: TIDA-01606E5_Gate Driver_Gate Drive power supply_Pg1 (10 pins), TIDA-01606E5_Gate Driver_Gate Drive power supply_Pg2 (5 pins), TIDA-01606E5_Gate Driver_Isolated Gate Driver_Pg4 (J401.10 R403.2)
-4V_BOT: TIDA-01606E5_Gate Driver_Gate Drive power supply_Pg1 (21 pins), TIDA-01606E5_Gate Driver_Isolated Gate Driver_Pg3 (5 pins)
-4V_MID: TIDA-01606E5_Gate Driver_Gate Drive power supply_Pg2 (21 pins), TIDA-01606E5_Gate Driver_Isolated Gate Driver_Pg4 (R421.2 R422.2)
-4V_TOP: TIDA-01606E5_Gate Driver_Gate Drive power supply_Pg1 (21 pins), TIDA-01606E5_Gate Driver_Isolated Gate Driver_Pg3 (5 pins)
GATE_BOT: TIDA-01606E5_Gate Driver_Isolated Gate Driver_Pg3 (R323.2 R324.2 U302.7), TIDA-01606E5_Gate Driver_Isolated Gate Driver_Pg4 (J403.4)
GATE_TOP: TIDA-01606E5_Gate Driver_Isolated Gate Driver_Pg3 (R307.2 R308.2 U301.7), TIDA-01606E5_Gate Driver_Isolated Gate Driver_Pg4 (J402.4)
GND: TIDA-01606E5_Gate Driver_Gate Drive power supply_Pg1 (36 pins), TIDA-01606E5_Gate Driver_Gate Drive power supply_Pg2 (18 pins), TIDA-01606E5_Gate Driver_Isolated Gate Driver_Pg3 (18 pins), TIDA-01606E5_Gate Driver_Isolated Gate Driver_Pg4 (23 pins)
GND_BOT: TIDA-01606E5_Gate Driver_Gate Drive power supply_Pg1 (C113.1 R112.2 R115.2), TIDA-01606E5_Gate Driver_Isolated Gate Driver_Pg3 (10 pins), TIDA-01606E5_Gate Driver_Isolated Gate Driver_Pg4 (J403.3)
GND_MID: TIDA-01606E5_Gate Driver_Gate Drive power supply_Pg2 (C205.1 R203.2 R206.2), TIDA-01606E5_Gate Driver_Isolated Gate Driver_Pg4 (10 pins)
GND_TOP: TIDA-01606E5_Gate Driver_Gate Drive power supply_Pg1 (C105.1 R103.2 R106.2), TIDA-01606E5_Gate Driver_Isolated Gate Driver_Pg3 (10 pins), TIDA-01606E5_Gate Driver_Isolated Gate Driver_Pg4 (J402.3)
PWM1_B: TIDA-01606E5_Gate Driver_Isolated Gate Driver_Pg3 (R301.1 R315.2), TIDA-01606E5_Gate Driver_Isolated Gate Driver_Pg4 (PWM401.1 R411.2 U401.3)
PWM2_B: TIDA-01606E5_Gate Driver_Isolated Gate Driver_Pg3 (R316.1 R317.2), TIDA-01606E5_Gate Driver_Isolated Gate Driver_Pg4 (PWM402.1 R410.2 U401.6)
DESAT_BOT: TIDA-01606E5_Gate Driver_Isolated Gate Driver_Pg3 (D302.1), TIDA-01606E5_Gate Driver_Isolated Gate Driver_Pg4 (J403.1)
DESAT_TOP: TIDA-01606E5_Gate Driver_Isolated Gate Driver_Pg3 (D301.1), TIDA-01606E5_Gate Driver_Isolated Gate Driver_Pg4 (J402.1)
FLT: TIDA-01606E5_Gate Driver_Isolated Gate Driver_Pg3 (R304.1 R320.1 U301.13 U302.13), TIDA-01606E5_Gate Driver_Isolated Gate Driver_Pg4 (FLT401.1 J401.7 R401.1 R404.1)
RDY: TIDA-01606E5_Gate Driver_Isolated Gate Driver_Pg3 (R303.1 R319.1 U301.12 U302.12), TIDA-01606E5_Gate Driver_Isolated Gate Driver_Pg4 (C401.1 J401.5 RDY401.1)
RST: TIDA-01606E5_Gate Driver_Isolated Gate Driver_Pg3 (R310.1 R326.1), TIDA-01606E5_Gate Driver_Isolated Gate Driver_Pg4 (C402.1 J401.3 RST401.1)

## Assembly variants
001: not fitted FID601 FID602 FID603 J401 J402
